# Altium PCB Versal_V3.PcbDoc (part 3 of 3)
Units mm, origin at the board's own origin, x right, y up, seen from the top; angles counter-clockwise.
Board outline 164.5 x 88.9 mm, 8 copper layers (Top Layer, Layer 2 [GND], Layer 3 [GND/OUT], Layer 4 [12V/GND], Layer 5 [GND/VOUT], Layer 6 [GND], Layer 7 [GND], Bottom Layer), stack 1.562 mm thick; 243 components, 69 nets, 695 pads, 1061 vias.
Unrouted connection lines stored in the file: 8.
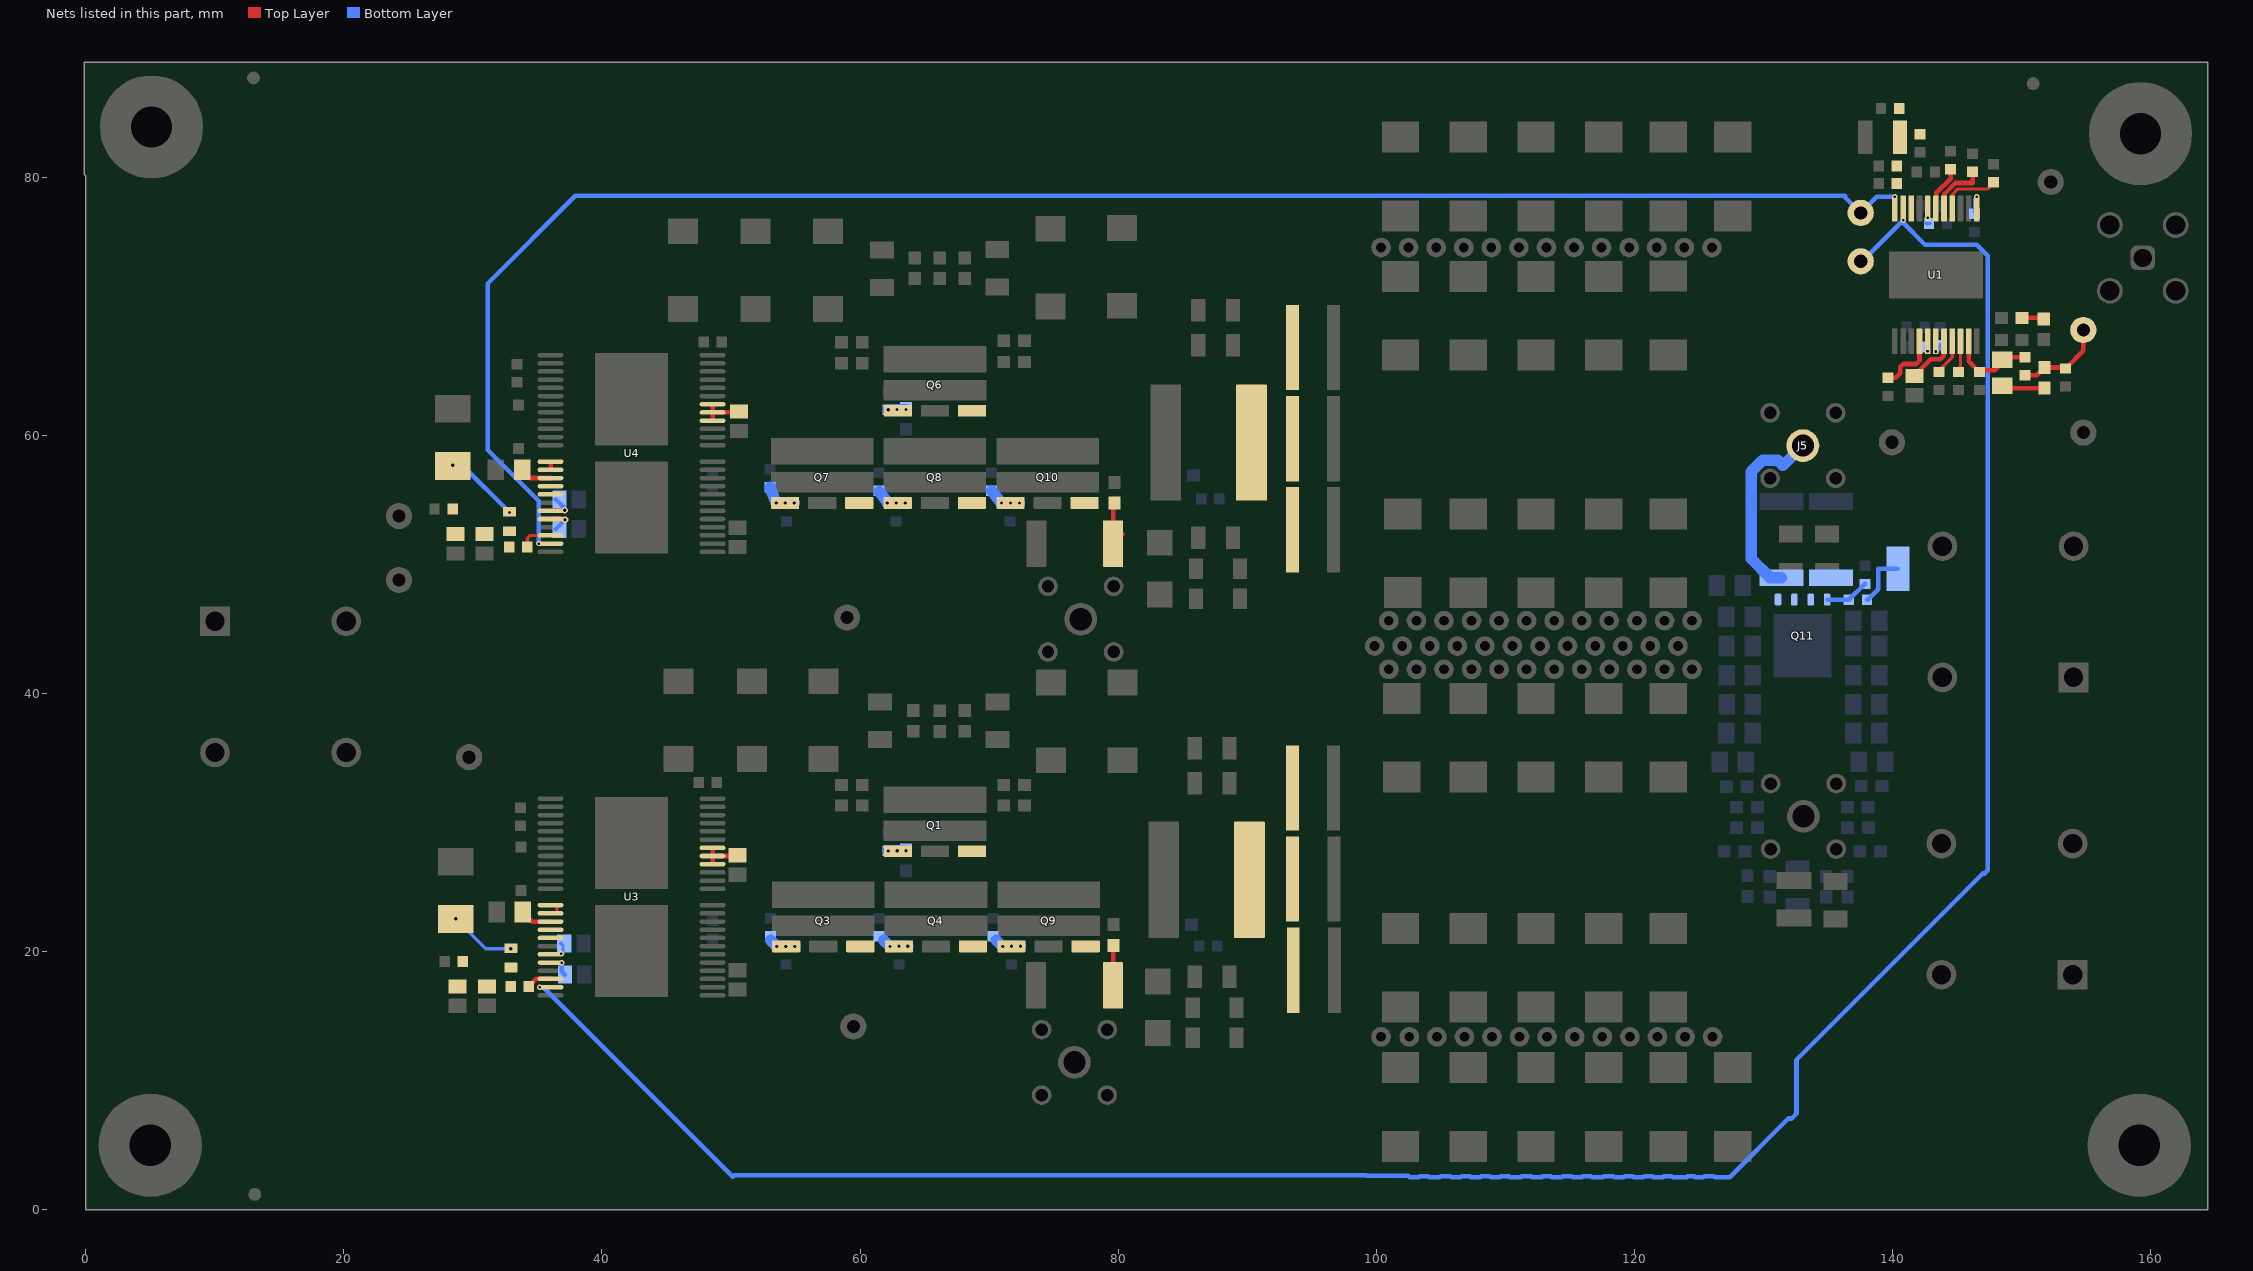
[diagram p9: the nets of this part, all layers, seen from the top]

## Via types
v1: diameter 0.508, hole 0.254, Top Layer to Bottom Layer, 951 vias
v2: diameter 0.5, hole 0.2, Top Layer to Bottom Layer, tented both sides, 60 vias
v3: diameter 0.5, hole 0.2, Top Layer to Bottom Layer, 34 vias
v4: diameter 0.406, hole 0.203, Top Layer to Bottom Layer, 16 vias

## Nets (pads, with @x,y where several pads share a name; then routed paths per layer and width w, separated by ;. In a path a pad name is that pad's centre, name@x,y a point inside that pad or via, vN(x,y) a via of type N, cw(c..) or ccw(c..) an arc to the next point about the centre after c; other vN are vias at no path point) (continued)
NetC1_1: C1.1 U1.18 | length 4
  Top Layer w0.356: C1.1@141.677,64.87 141.919,64.87 142.957,65.908 143.692,65.908 143.945,66.161 143.945,67.289 U1.18@143.981,67.289
NetC2_1: C2.1 C3.1 C4.1 R1.2 R2.2 U1.9
NetC6_1: C6.1 U1.5 | length 4.4
  Top Layer w0.356: U1.5@143.981,77.579 144.018,77.616 144.018,78.708 144.864,79.554 146.196,79.554 C6.1@146.196,80.318
NetC8_2: C8.2 U1.20 | length 2.3
  Top Layer w0.254: C8.2@145.097,65.017 145.251,65.172 U1.20@145.251,67.289
NetC9_2: C9.2 U1.15 | length 4.8
  Top Layer w0.356: C9.2@139.656,64.459 140.246,64.459 140.596,64.809 140.596,65.312 140.819,65.535 141.825,65.535 142.076,65.786 U1.15@142.076,67.289
NetC11_1: C11.1 R9.1 | length 1.5
  Top Layer w0.356: R9.1@149.936,69.103 151.207,69.103 C11.1@151.363,68.947
NetC18_1: C18.1 C19.1 R14.1 R23.1 R24.1 U3.16 U3.17
NetC20_1: C20.1 U3.15 | length 2.5
  Top Layer w0.356: C20.1@33.866,23.072 34.603,22.334 U3.15@36.017,22.334
NetC21_1: C21.1 U3.40 U3.41 U3.42 | length 3.2
  Top Layer w0.356: U3.40@48.567,26.779 U3.41@48.567,27.414 ; U3.42@48.567,28.049 U3.41@48.567,27.414 ; C21.1@50.497,27.468 50.443,27.414 U3.41@48.567,27.414
NetC25_1: C25.1 C26.1 R18.1 R45.1 R46.1 U4.16 U4.17
NetC27_1: C27.1 U4.15 | length 2.5
  Top Layer w0.356: C27.1@33.817,57.334 34.452,56.699 U4.15@36.017,56.699
NetC28_1: C28.1 U4.40 U4.41 U4.42 | length 3.3
  Top Layer w0.356: U4.40@48.567,61.144 U4.41@48.567,61.779 ; U4.42@48.567,62.414 U4.41@48.567,61.779 ; C28.1@50.605,61.85 50.534,61.779 U4.41@48.567,61.779
NetC89_1: C89.1 R67.1 | length 3.4
  Top Layer w0.356: C89.1@148.496,63.837 148.673,63.659 R67.1@151.773,63.659
NetC110_2: C110.2 R100.2 | length 4.2
  Top Layer w0.356: C110.2@79.714,54.761 79.611,54.658 R100.2@79.611,51.623 R100.2@80.329,52.341
NetC111_2: C111.2 R101.2 | length 2.9
  Top Layer w0.356: R101.2@79.608,17.6 79.608,20.468 C111.2@79.631,20.491
NetD1_2: D1.2 R23.2 | length 5.2
  Bottom Layer w0.254: v1(28.669,22.547) 30.99,20.225 v1(32.941,20.225)
NetD5_2: D5.2 R45.2 | length 6
  Top Layer w0.254: D5.2@28.429,57.644 v1(28.429,57.694)
  Bottom Layer w0.356: v1(28.429,57.694) 29.173,57.694 v1(32.842,54.025)
NetJ5_1: J5.1 Q11.1 Q11.2 Q11.3 R96.2 R97.2 | length 14.9
  Bottom Layer w0.889: R97.2@131.381,48.973 130.52,48.973 129.033,50.46 129.033,57.195 129.921,58.083 131.089,58.083 131.502,57.67 J5.1@133.045,59.213
NetL1_2: L1.2 R28.1 R29.1 R30.1
NetL2_2: L2.2 R31.1 R32.1 R33.1
NetQ1_1: Q1.1 Q1.2 R70.2 R71.2 | length 1.4
  Bottom Layer w0.889: R71.2@62.171,27.813 v1(62.867,27.813) v1(63.563,27.813)
  other v1: 62.178,27.8
NetQ3_1: Q3.1 Q3.2 R74.2 R75.2 | length 2.4
  Bottom Layer w0.356: R75.2@53.068,20.871 R75.2@53.068,21.188
  Bottom Layer w0.889: R75.2@53.068,20.871 v1(53.543,20.396) ; v1@53.543,20.409 v1(54.232,20.409) v1(54.928,20.409)
NetQ4_1: Q4.1 Q4.2 R76.2 R77.2 | length 2.1
  Bottom Layer w0.889: R77.2@61.841,20.875 v1(62.316,20.4) ; v1@62.316,20.413 v1(63.005,20.413) v1(63.701,20.413)
NetQ6_1: Q6.1 Q6.2 R83.2 R84.2 | length 1.4
  Bottom Layer w0.889: R84.2@62.164,62.003 v1(62.86,62.003) v1(63.556,62.003)
  other v1: 62.171,61.99
NetQ7_1: Q7.1 Q7.2 R87.2 R88.2 | length 2.4
  Bottom Layer w0.889: R88.2@53.024,55.986 v1(53.502,54.757) ; 53.84,54.77 v1(54.191,54.77) v1(54.887,54.77)
NetQ8_1: Q8.1 Q8.2 R89.2 R90.2 | length 2.2
  Bottom Layer w0.889: R90.2@61.498,55.63 61.973,54.98 ; v1@62.104,54.77 v1(62.793,54.77) v1(63.489,54.77)
  other v1: 62.104,54.757
NetQ9_1: Q9.1 Q9.2 R78.2 R79.2 | length 2.1
  Bottom Layer w0.889: R79.2@70.566,20.875 v1(71.041,20.4) ; v1@71.041,20.413 v1(71.73,20.413) v1(72.426,20.413)
NetQ10_1: Q10.1 Q10.2 R91.2 R92.2 | length 2.6
  Bottom Layer w0.889: R92.2@70.196,55.705 v1(70.958,54.757) ; v1@70.958,54.77 v1(71.647,54.77) v1(72.343,54.77)
NetQ11_4: Q11.4 R94.2 R95.2 | length 3.4
  Bottom Layer w0.356: Q11.4@134.924,47.281 136.597,47.281 R94.2@136.61,47.268 137.833,48.491 R95.2@137.86,48.491
NetR3_1: R3.1 U1.16
  other v4: 142.704,66.527
NetR4_1: R4.1 R7.2 R67.2 TP5.1 | length 6.9
  Top Layer w0.356: R7.2@150.24,64.657 151.171,64.657 R67.2@151.773,65.259 R4.1@153.373,65.259 ; R4.1@153.4,65.186 154.771,66.557 TP5.1@154.771,68.172
NetR5_1: R5.1 U1.17 | length 0.6
  Bottom Layer w0.356: v4(143.346,66.497) 143.67,66.821 R5.1@143.67,66.997
NetR8_1: R8.1 U1.1 | length 1.3
  Bottom Layer w0.254: R8.1@146.347,77.265 146.347,78.309 v4(146.524,78.486)
NetR11_2: R11.2 U1.4 | length 4.6
  Top Layer w0.254: U1.4@144.616,77.579 144.616,78.657 145.056,79.097 147.404,79.097 R11.2@147.825,79.518
NetR12_2: R12.2 U1.7 | length 1.4
  Top Layer w0.356: U1.7@142.711,77.579 142.711,76.88 v4(142.715,76.877)
  Bottom Layer w0.356: v4(142.715,76.877) 142.641,76.803 142.641,76.433 R12.2@142.816,76.433
NetR13_2: R13.2 U1.19 | length 2.7
  Top Layer w0.254: R13.2@143.58,65.017 144.616,66.053 U1.19@144.616,67.289
NetR14_2: R14.2 U3.22 | length 1.9
  Top Layer w0.356: R14.2@34.33,17.298 34.922,17.889 U3.22@36.017,17.889
NetR15_2: R15.2 U3.19 | length 0.9
  Bottom Layer w0.254: R15.2@36.81,20.644 36.986,20.469 v4@36.986,19.778
  other v4: 36.84,19.836
NetR16_2: R16.2 U3.20 | length 1
  Bottom Layer w0.356: v4(36.876,19.15) 36.876,18.478 R16.2@37.126,18.229
NetR18_2: R18.2 U4.22 | length 2.6
  Top Layer w0.254: R18.2@34.221,51.352 34.221,52.015 34.461,52.254 U4.22@36.017,52.254
NetR19_2: R19.2 U4.19 | length 2.2
  Top Layer w0.356: U4.19@36.017,54.159 37.07,54.159 v1(37.119,54.208)
  Bottom Layer w0.356: R19.2@36.434,55.034 37.119,54.35 v1(37.119,54.208)
NetR20_2: R20.2 U4.20 | length 2.1
  Top Layer w0.356: U4.20@36.017,53.524 37.066,53.524 v1(37.134,53.455)
  Bottom Layer w0.356: R20.2@36.434,52.752 37.134,53.452 v1(37.134,53.455)
NetR94_1: R94.1 TP13.1 | length 4.3
  Bottom Layer w0.356: R94.1@138.01,47.268 138.071,47.268 138.891,48.089 138.891,49.659 140.4,49.659 TP13.1@140.4,49.663
NetR99_1: R99.1 U1.6 | length 3.5
  Top Layer w0.356: U1.6@143.346,77.579 143.346,78.292 143.383,78.329 143.383,78.791 144.486,79.894 R99.1@144.486,80.621
NetU3_13: U3.13 U3.14 | length 0.6
  Top Layer w0.254: U3.14@36.518,22.969 U3.13@36.518,23.604
NetU4_13: U4.13 U4.14 | length 0.6
  Top Layer w0.356: U4.14@36.017,57.334 U4.13@36.017,57.969
OUTA: TP3.1 U1.10 U3.23 | length 191.7
  Bottom Layer w0.356: v4(35.172,17.254) 35.436,17.254 50.13,2.56 50.237,2.667 99.193,2.667 99.221,2.638 102.478,2.638 102.58,2.536 103.297,2.536 103.373,2.612 104.004,2.612 104.08,2.536 104.913,2.536 104.989,2.612 105.735,2.612 105.811,2.536 106.528,2.536 106.604,2.612 107.235,2.612 107.311,2.536 108.047,2.536 108.123,2.612 108.773,2.612 108.849,2.536 109.566,2.536 109.642,2.612 110.273,2.612 110.349,2.536 111.182,2.536 111.258,2.612 112.003,2.612 112.08,2.536 112.797,2.536 112.873,2.612 113.503,2.612 113.58,2.536 114.359,2.536 114.435,2.612 115.127,2.612 115.203,2.536 115.921,2.536 115.997,2.612 116.627,2.612 116.703,2.536 117.536,2.536 117.612,2.612 118.358,2.612 118.434,2.536 119.152,2.536 119.228,2.612 119.858,2.612 119.934,2.536 120.671,2.536 120.747,2.612 121.396,2.612 121.472,2.536 122.19,2.536 122.266,2.612 122.896,2.612 122.972,2.536 124.025,2.536 124.101,2.612 124.627,2.612 124.703,2.536 125.316,2.536 125.392,2.612 126.127,2.612 126.203,2.536 127.375,2.536 131.917,7.079 132.18,7.079 132.552,7.451 132.552,11.629 146.984,26.061 147.133,26.061 147.372,26.3 147.372,73.935 146.524,74.784 142.503,74.784 140.82,76.466 v4(140.82,76.679) 137.634,73.492 TP3.1@137.524,73.492
OUTB: TP4.1 U1.11 U4.23 | length 134.6
  Bottom Layer w0.356: v4(35.095,51.619) 35.095,54.922 31.15,58.867 31.15,71.768 37.943,78.562 136.305,78.562 ; 136.305,78.461 TP4.1@137.524,77.242 138.768,78.486 v4(140.171,78.486)
VSENSE: C89.2 R7.1 R10.2 U1.21 | length 6.8
  Top Layer w0.356: U1.21@145.886,67.289 145.886,65.759 R10.2@146.728,64.917 146.728,65.034 147.927,65.034 148.496,65.603 148.95,66.057 R7.1@150.24,66.057
pads on no net: FID1.1 FID2.1 FID3.1 H1.1 H2.1 H3.1 H4.1 H5.0 H6.0 H7.0 H8.0 LBL1.0 Q11.9@131.589,42.866 Q11.9@131.589,44.206 Q11.9@131.589,45.546 Q11.9@133.019,42.866 Q11.9@133.019,44.106 Q11.9@133.019,44.206 Q11.9@133.019,45.546 Q11.9@134.449,42.866 Q11.9@134.449,44.206 Q11.9@134.449,45.546 U1.2 U1.3 U1.12 U1.13

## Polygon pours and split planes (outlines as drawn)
GND on Top Layer "TOP_LAYER_GND_P012" (solid, pour order 12): 73.637,33.483 73.296,33.824 73.296,33.858 72.43,33.858 71.832,33.26 71.832,30.396 72.276,29.985 73.381,29.985 73.637,30.24
GND on Top Layer "TOP_LAYER_GND_P015" (solid, pour order 15): 57.629,30.369 57.97,30.028 57.97,29.994 58.836,29.994 59.433,30.591 59.433,33.456 58.99,33.867 57.885,33.867 57.629,33.611
GND on Top Layer "TOP_LAYER_GND_P019" (solid, pour order 19): 73.803,68.047 73.462,68.388 73.462,68.422 72.596,68.422 71.999,67.825 71.999,64.96 72.442,64.549 73.547,64.549 73.803,64.805
GND on Top Layer "TOP_LAYER_GND_P018" (solid, pour order 18): 57.413,64.864 57.754,64.523 57.754,64.49 58.62,64.49 59.217,65.087 59.217,67.952 58.774,68.362 57.668,68.362 57.413,68.107
GND on Top Layer "TOP_LAYER_GND_P102" (solid, remove dead copper, pour order 102): 136.61,58.224 136.538,58.296 130.469,58.296 129.431,57.258 129.431,53.88 132.123,51.187 136.61,51.187 136.61,40.269 138.195,38.684 161.381,38.684 163.4,40.683 163.4,87.219 136.61,87.219
GND on Top Layer "TOP_LAYER_GND_P098" (solid, remove dead copper, pour order 98): 98.074,46.488 101.387,49.801 126.308,49.801 127.492,48.617 127.492,37.958 126.483,36.95 101.572,36.95 98.074,40.447
NetL1_2 on Top Layer "TOP_LAYER_NETL1_2_P093" (solid, remove dead copper, pour order 93): 88.842,20.934 92.291,17.486 92.291,13.832 94.29,13.832 94.29,38.497 92.569,38.497 92.569,34.349 88.842,30.623
ASW1 on Top Layer "TOP_LAYER_ASW1_P086" (solid, remove dead copper, pour order 86): 32.905,24.675 33.716,23.863 49.932,23.863 49.932,23.613 52.095,21.45 80.542,21.45 80.542,17.977 82.989,15.531 85.514,15.531 85.514,30.128 50.304,30.128 49.752,29.575 49.752,26.297 47.709,26.297 47.313,26.694 47.313,32.491 33.793,32.491 32.905,31.603
BP5L1 on Top Layer "TOP_LAYER_BP5L1_P022" (solid, pour order 22): 47.322,19.775 47.556,20.008 52.18,20.008 52.397,19.791 52.397,18.35 52.119,18.072 47.567,18.072 47.322,18.316 47.322,19.775
BP5L2 on Top Layer "TOP_LAYER_BP5L2_P037" (solid, pour order 37): 47.347,54.173 47.581,54.406 52.205,54.406 52.422,54.189 52.422,52.748 52.144,52.47 47.592,52.47 47.347,52.714 47.347,54.173
GND on Top Layer "TOP_LAYER_GND_P099" (solid, remove dead copper, pour order 99): 126.386,70.939 126.828,70.497 126.828,66.174 128.154,64.848 131.091,64.848 133.111,66.869 133.111,78.071 131.344,79.839 101.2,79.839 99.772,78.41 99.772,72.369 101.202,70.939
GND on Top Layer "TOP_LAYER_GND_P101" (solid, remove dead copper, pour order 101): 125.38,17.872 126.205,18.697 126.205,22.42 126.932,23.147 136.638,23.147 136.638,15.35 128.321,8.887 101.64,8.887 99.849,10.677 99.849,16.719 101.003,17.872
ASW2 on Top Layer "TOP_LAYER_ASW2_P083" (solid, remove dead copper, pour order 83): 79.451,55.912 79.451,51.672 80.227,50.897 84.94,50.897 84.94,64.113 49.76,64.113 49.76,61.851 49.76,61.013 47.585,61.013 47.585,66.734 33.193,66.734 33.003,66.541 33.003,58.798 33.741,58.059 49.426,58.059 51.555,56.002
GND on Top Layer "TOP_LAYER_GND_P103" (solid, remove dead copper, pour order 103): 87.275,-0.088 0,-0.088 0,88.312 87.275,88.312
LOL_GATE4 on Top Layer "TOP_LAYER_LOL_GATE4_P051" (solid, pour order 51): 47.377,58.008 47.61,58.241 52.235,58.241 52.452,58.024 52.452,56.583 52.174,56.305 47.621,56.305 47.377,56.549 47.377,58.008
LOH_GATE2 on Top Layer "TOP_LAYER_LOH_GATE2_P053" (solid, pour order 53): 47.347,21.711 47.581,21.945 52.205,21.945 52.422,21.728 52.422,20.286 52.144,20.008 47.592,20.008 47.347,20.253 47.347,21.711
HOH_GATE3 on Top Layer "TOP_LAYER_HOH_GATE3_P054" (solid, pour order 54): 47.377,64.356 47.61,64.59 52.235,64.59 52.452,64.373 52.452,62.932 52.174,62.654 47.621,62.654 47.377,62.898 47.377,64.357
HOL_GATE3 on Top Layer "TOP_LAYER_HOL_GATE3_P063" (solid, pour order 63): 48.2,66.622 48.297,66.719 48.297,67.734 48.553,67.99 49.435,67.99 49.627,67.798 49.627,66.829 49.852,66.605 52.259,66.622 52.476,66.405 52.476,64.963 52.197,64.684 47.647,64.684 47.401,64.93 47.401,66.405 47.639,66.622
HOH_GATE1 on Top Layer "TOP_LAYER_HOH_GATE1_P064" (solid, pour order 64): 47.377,29.991 47.61,30.225 52.235,30.225 52.452,30.008 52.452,28.566 52.174,28.288 47.621,28.288 47.377,28.533 47.377,29.991
HOL_GATE1 on Top Layer "TOP_LAYER_HOL_GATE1_P066" (solid, pour order 66): 48.2,32.257 48.297,32.354 48.297,33.369 48.553,33.625 49.435,33.625 49.627,33.433 49.627,32.464 49.852,32.239 52.259,32.257 52.476,32.04 52.476,30.598 52.197,30.319 47.647,30.319 47.401,30.565 47.401,32.04 47.639,32.257
BOOT1 on Top Layer "TOP_LAYER_BOOT1_P020" (solid, remove dead copper, pour order 20): 34.404,28.786 34.581,28.963 36.99,28.963 36.99,30.192 36.812,30.37 27.386,30.37 27.051,30.034 27.037,25.607 34.404,25.607
NetL2_2 on Top Layer "TOP_LAYER_NETL2_2_P071" (solid, remove dead copper, pour order 71): 88.82,54.3 88.893,54.3 91.573,51.62 91.573,47.182 93.096,47.182 94.306,48.392 94.306,71.848 92.445,71.848 92.445,67.988 88.82,64.363
NetC25_1 on Top Layer "TOP_LAYER_NETC25_1_P072" (solid, remove dead copper, pour order 72): 27.729,55.992 28.054,56.318 37.083,56.318 37.376,56.025 37.376,55.384 36.98,54.988 32.117,54.988 32.117,53.325 32.446,53.325 32.517,53.254 32.588,53.325 33.167,53.325 33.317,53.175 33.317,50.963 33.182,50.827 32.321,50.827 32.321,51.778 28.17,51.778 27.729,52.22
BOOT2 on Top Layer "TOP_LAYER_BOOT2_P073" (solid, remove dead copper, pour order 73): 37.327,64.807 37.478,64.655 37.478,63.425 37.384,63.331 34.631,63.331 34.622,63.321 34.622,59.139 27.132,59.139 26.794,59.477 26.81,64.807
NetC18_1 on Top Layer "TOP_LAYER_NETC18_1_P082" (solid, remove dead copper, pour order 82): 28.187,21.746 28.422,21.981 37.633,21.981 37.834,21.779 37.834,21.138 37.438,20.742 32.576,20.742 32.576,19.079 32.905,19.079 32.972,19.079 33.047,19.079 33.626,19.079 34.09,18.615 34.09,17.031 33.64,16.581 32.78,16.581 28.666,16.581 28.187,17.06
12V on Top Layer "TOP_LAYER_12V_P088" (solid, remove dead copper, pour order 88): 71.728,62.69 71.728,67.787 72.479,68.539 82.277,68.539 82.786,69.013 82.786,72.913 2.688,72.913 2.857,60.904 2.857,29.363 16.7,29.363 16.7,51.077 25.568,51.077 27.151,52.66 27.386,52.66 27.386,62.667 27.254,62.69
12V on Top Layer "TOP_LAYER_12V_P089" (solid, remove dead copper, pour order 89): 72.09,29.467 72.09,32.92 72.43,33.26 82.484,33.26 83.129,33.906 83.129,38.344 31.468,38.344 31.468,41.665 29.52,43.613 2.897,43.613 2.738,40.832 2.897,29.467 2.738,29.307 2.738,19.316 3.866,18.187 28.369,18.187 28.369,29.425 28.52,29.467
NetC2_1 on Top Layer "TOP_LAYER_NETC2_1_P092" (solid, remove dead copper, pour order 92): 140.04,85.889 139.802,85.651 139.802,79.061 139.802,76.546 142.776,76.546 142.776,85.729 142.616,85.889
0V8 on Top Layer "TOP_LAYER_0V8_P104" (solid, remove dead copper, pour order 104): 87.612,88.666 164.468,88.666 164.468,1.061 87.612,1.061
LOL_GATE2 on Top Layer "TOP_LAYER_LOL_GATE2_P041" (solid, pour order 41): 47.377,23.641 47.61,23.875 52.235,23.875 52.452,23.658 52.452,22.216 52.174,21.938 47.621,21.938 47.377,22.183 47.377,23.641
LOH_GATE4 on Top Layer "TOP_LAYER_LOH_GATE4_P048" (solid, pour order 48): 47.347,56.078 47.581,56.311 52.205,56.311 52.422,56.094 52.422,54.653 52.144,54.375 47.592,54.375 47.347,54.619 47.347,56.078
GND on Layer 2 [GND] "LAYER_2_[GND]_GND_P052" (solid, remove dead copper, pour order 52): 0,88.9 0,-0.128 164.272,-0.128 164.506,0.106 164.506,88.969 0.069,88.969
GND on Layer 7 [GND] "LAYER_7_[GND]_GND_P056" (solid, remove dead copper, pour order 56): 0.547,88.253 163.753,88.253 163.753,0.647 0.647,0.647 0.647,88.153
GND on Layer 3 [GND/OUT] "LAYER_3_[GND/OUT]_GND_P067" (solid, remove dead copper, pour order 67): 0.697,88.203 0.807,88.312 89.911,88.312 89.911,0.754 89.804,0.647 0.647,0.647 0.647,88.153
0V8 on Layer 3 [GND/OUT] "LAYER_3_[GND/OUT]_0V8_P057" (solid, remove dead copper, pour order 57): 87.549,88.253 163.753,88.253 163.753,0.647 87.549,0.647
GND on Layer 5 [GND/VOUT] "LAYER_5_[GND/VOUT]_GND_P069" (solid, remove dead copper, pour order 69): 0.804,88.253 90.1,88.253 90.1,0.739 90.192,0.647 0.647,0.647 0.647,88.153 0.697,88.203
0V8 on Layer 5 [GND/VOUT] "LAYER_5_[GND/VOUT]_0V8_P058" (solid, remove dead copper, pour order 58): 87.549,88.253 163.753,88.253 163.753,0.647 87.549,0.647
12V on Layer 4 [12V/GND] "LAYER_4_[12V/GND]_12V_P060" (solid, remove dead copper, pour order 60): 83.883,39.024 83.203,38.344 21.9,38.344 21.9,60.075 25.412,63.586 83.883,63.586 83.883,70.47 0.694,70.47 0.694,29.807 83.883,29.807
GND on Layer 4 [12V/GND] "LAYER_4_[12V/GND]_GND_P068" (solid, remove dead copper, pour order 68): 0.647,88.153 0.747,88.253 163.753,88.253 163.753,0.647 0.647,0.647 0.647,88.153 0.697,88.203
0V8 on Bottom Layer "BOTTOM_LAYER_0V8_P077" (solid, pour order 77): 130.408,46.558 129.706,47.26 129.706,49.435 129.431,49.71 127.653,49.71 127.653,49.666 127.38,49.393 127.38,25.735 127.275,25.63 128.021,24.885 128.021,24.693 137.406,24.693 138.335,25.621 138.335,46.558
NetJ5_1 on Bottom Layer "BOTTOM_LAYER_NETJ5_1_P097" (solid, remove dead copper, pour order 97): 130.814,46.845 136.933,46.845 136.933,50.179 130.239,50.179 129.706,49.646 129.706,46.845
LOL_GATE4 on Bottom Layer "BOTTOM_LAYER_LOL_GATE4_P081" (solid, pour order 81): 47.356,58.008 47.59,58.241 52.214,58.241 52.431,58.024 52.431,56.583 52.153,56.305 47.601,56.305 47.356,56.549 47.356,58.008
LOH_GATE4 on Bottom Layer "BOTTOM_LAYER_LOH_GATE4_P080" (solid, pour order 80): 49.372,56.336 52.214,56.336 52.431,56.119 52.431,54.678 52.153,54.4 49.372,54.4
HOL_GATE3 on Bottom Layer "BOTTOM_LAYER_HOL_GATE3_P087" (solid, pour order 87): 47.401,66.388 47.635,66.622 52.259,66.622 52.476,66.405 52.476,64.964 52.198,64.686 47.645,64.686 47.401,64.93 47.401,66.389
HOH_GATE3 on Bottom Layer "BOTTOM_LAYER_HOH_GATE3_P085" (solid, pour order 85): 47.377,64.356 47.61,64.59 52.235,64.59 52.452,64.373 52.452,62.932 52.174,62.654 47.621,62.654 47.377,62.898 47.377,64.357
LOH_GATE2 on Bottom Layer "BOTTOM_LAYER_LOH_GATE2_P062" (solid, pour order 62): 49.372,21.97 52.214,21.97 52.431,21.753 52.431,20.311 52.153,20.033 49.372,20.033
LOL_GATE2 on Bottom Layer "BOTTOM_LAYER_LOL_GATE2_P090" (solid, pour order 90): 47.356,23.641 47.59,23.875 52.214,23.875 52.431,23.658 52.431,22.216 52.153,21.938 47.601,21.938 47.356,22.183 47.356,23.641
HOH_GATE1 on Bottom Layer "BOTTOM_LAYER_HOH_GATE1_P091" (solid, pour order 91): 47.377,29.991 47.61,30.225 52.235,30.225 52.452,30.008 52.452,28.566 52.174,28.288 47.621,28.288 47.377,28.533 47.377,29.991
HOL_GATE1 on Bottom Layer "BOTTOM_LAYER_HOL_GATE1_P096" (solid, pour order 96): 47.401,32.023 47.635,32.257 52.259,32.257 52.476,32.04 52.476,30.599 52.198,30.32 47.645,30.32 47.401,30.565 47.401,32.023
GND on Bottom Layer "BOTTOM_LAYER_GND_P100" (solid, remove dead copper, pour order 100): 0.683,88.331 0.783,88.431 163.788,88.431 163.788,0.825 0.683,0.825 0.683,88.331 0.583,88.431
GND on Layer 6 [GND] "LAYER_6_[GND]_GND_P070" (solid, remove dead copper, pour order 70): 0.752,88.257 0.757,88.253 163.753,88.253 163.753,0.647 0.647,0.647 0.647,88.153

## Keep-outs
Keep-Out Layer:
  text ".Layer_Name" at 14.656,-21.806 h1.52

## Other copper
Top Layer:
  pour cut-out: 139.373,75.665 147.319,75.665 147.319,69.204 139.373,69.204
  text ".Layer_Name" at 14.656,-21.806 h1.52
Bottom Layer:
  text ".Layer_Name" at 14.656,-21.806 h1.52

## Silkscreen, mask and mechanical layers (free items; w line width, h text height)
Top Overlay:
  text "TIDA-010958" at 21.667,7.594 h1.5
  text ".Layer_Name" at 14.656,-21.806 h1.52
Bottom Overlay:
  text ".Layer_Name" at 14.656,-21.806 h1.52
Top Paste:
  text ".Layer_Name" at 14.656,-21.806 h1.52
Bottom Paste:
  text ".Layer_Name" at 14.656,-21.806 h1.52
Top Solder:
  text ".Layer_Name" at 14.656,-21.806 h1.52
  text ".Layer_Name" at 14.656,-21.806 h1.52
Bottom Solder:
  text ".Layer_Name" at 14.656,-21.806 h1.52
Drill Guide:
  text ".Layer_Name" at 14.656,-21.806 h1.52
M1 Board Outline:
  lines w0.254: 0,-0.088 164.4,0 164.506,88.969 118.5,88.875 ; 0,0 0,88.697 ; 0,88.9 98.477,88.875 ; 99.073,88.955 110.195,88.98 119.095,88.955
  text ".Layer_Name" at 14.656,-21.806 h1.52
M2 Board Dimensions:
  rectangle: 0,-6.985 3.175,-3.81
  rectangle: 3.175,-10.16 12.7,-6.985
  lines w0.178: 0,-6.985 25.4,-6.985 ; 3.175,-10.16 3.175,-3.81 ; 6.35,-10.16 6.35,-3.81 ; 12.7,-10.16 12.7,-3.81 ; 19.05,-10.16 19.05,-3.81 ; 0,-10.16 0,-3.81 25.4,-3.81 25.4,-10.16 0,-10.16
  text ".Layer_Name" at 14.656,-21.806 h1.52
M3 3D STEP Top:
  text ".Layer_Name" at 14.656,-21.806 h1.52
M4 3D STEP Bottom:
  text ".Layer_Name" at 14.656,-21.806 h1.52
M5 Assembly Top:
  lines w0.254: -7.417,-23.626 160.223,-23.626 ; -7.417,-18.462 160.274,-18.462 ; -7.417,-13.297 -7.417,-28.791 94.31,-28.791 160.274,-28.791 160.274,-13.297 -7.404,-13.297 -7.404,-28.791 32.614,-28.791 ; 55.194,-28.791 55.194,-13.297 ; 87.376,-18.462 87.376,-13.297 ; 108.712,-18.462 108.712,-13.297 ; 124.511,-28.956 124.511,-23.804
  text "COMPONENTS MARKED 'DNP' SHOULD NOT BE POPULATED." at 29.299,-8.09 h0.64
  text "ASSEMBLY VARIANT:" at 29.286,-11.024 h0.64
  text ".VariantName" at 55.601,-11.024 h0.64
  text "PCB VIEWED FROM TOP SIDE" at -5.804,-16.654 h1.52
  text "BOARD #:" at 57.099,-16.654 h1.52
  text ".PRJ_Number" at 70.955,-16.654 h1.52
  text "REV:" at 92.405,-16.654 h1.52
  text ".PCB_Rev" at 99.809,-16.654 h1.52
  text "SVN REV:" at 113.69,-16.654 h1.52
  text ".VersionControl_RevNumber" at 126.543,-16.654 h1.52
  text "TID #:" at 57.099,-21.819 h1.52
  text ".TID" at 70.955,-21.819 h1.52
  text "PLOT NAME =" at -5.804,-27.034 h1.52
  text ".plot_File_Name" at 14.656,-27.034 h1.52
  text "GENERATED    :" at 57.15,-27.034 h1.52
  text ".Print_Date" at 79.235,-27.034 h1.52
  text ".Print_Time" at 97.752,-27.034 h1.52
  text "TEXAS INSTRUMENTS" at 129.87,-27.034 h1.52
M6 Assembly Bottom:
  lines w0.254: -7.429,-18.474 160.261,-18.474 ; -7.379,-23.639 160.261,-23.639 ; 28.334,-28.969 28.334,-23.817 ; 44.133,-18.474 44.133,-13.31 ; 65.468,-18.474 65.468,-13.31 ; 97.65,-28.804 97.65,-13.31 ; 120.231,-28.804 160.249,-28.804 160.249,-13.31 -7.429,-13.31 -7.429,-28.804 58.534,-28.804 160.261,-28.804 160.261,-13.31
  text "COMPONENTS MARKED 'DNP' SHOULD NOT BE POPULATED." at 154.991,-8.077 h0.64
  text ".VariantName" at 128.473,-11.024 h0.64
  text "ASSEMBLY VARIANT:" at 154.864,-11.024 h0.64
  text ".VersionControl_RevNumber" at 26.302,-16.667 h1.52
  text "SVN REV:" at 39.154,-16.667 h1.52
  text ".PCB_Rev" at 53.035,-16.667 h1.52
  text "REV:" at 60.439,-16.667 h1.52
  text ".PRJ_Number" at 81.89,-16.667 h1.52
  text "BOARD #:" at 95.745,-16.667 h1.52
  text "PCB VIEWED FROM BOTTOM SIDE" at 158.648,-16.667 h1.52
  text ".TID" at 81.89,-21.831 h1.52
  text "TID #:" at 95.745,-21.831 h1.52
  text "TEXAS INSTRUMENTS" at 22.974,-27.047 h1.52
  text ".Print_Time" at 55.093,-27.047 h1.52
  text ".Print_Date" at 73.609,-27.047 h1.52
  text "GENERATED    :" at 95.694,-27.047 h1.52
  text ".plot_File_Name" at 138.189,-27.047 h1.52
  text "PLOT NAME =" at 158.648,-27.047 h1.52
M9 Title Sheet:
  drawing of 57 lines, arcs and shapes, not listed
  text "1" at 18.792,204.127 h1.78
  text "2" at 82.182,204.127 h1.78
  text "3" at 145.411,204.127 h1.78
  text "4" at 209.08,204.127 h1.78
  text "5" at 272.555,204.127 h1.78
  text "6" at 336.182,204.127 h1.78
  text "A" at -10.579,175.095 h1.78
  text "A" at 365.341,175.095 h1.78
  text "B" at -10.579,114.643 h1.78
  text "B" at 365.341,114.643 h1.78
  text "C" at -10.579,54.318 h1.78
  text "C" at 365.341,54.318 h1.78
  text "PROJECT TITLE:" at 288.125,7.048 h1.14
  text ".PRJ_Title" at 289.395,3.662 h1.78
  text "DESIGNED FOR:" at 288.125,-0.597 h1.14
  text ".PRJ_Customer" at 289.395,-4.153 h1.78
  text "D" at -10.579,-5.88 h1.78
  text "D" at 365.341,-5.88 h1.78
  text "FILE NAME:" at 288.125,-8.217 h1.14
  text ".PCB_File_Name_No_Path" at 289.395,-11.265 h1.78
  text "Texas Instruments (TI) and/or its licensors do not warrant the accuracy or completeness of this specification" at 161.9,-15.376 h1.14
  text "ENGINEER:" at 288.125,-15.583 h1.14
  text "LAYOUT BY:" at 326.352,-15.583 h1.14
  text "or any information contained therein. TI and/or its licensors do not warrant that this design will meet" at 160.757,-18.237 h1.14
  text ".PRJ_Engineer" at 289.395,-19.52 h1.78
  text ".PCB_Layout" at 327.635,-19.52 h1.78
  text "the specifications, will be suitable for your application or fit for any particular purpose, or will operate in" at 160.757,-21.099 h1.14
  text ".Layer_Name" at 14.656,-21.806 h1.52
  text "ALTIUM DESIGNER VERSION:" at 326.352,-23.457 h1.14
  text "an implementation. TI and/or its licensors do not warrant that the design is production worthy. You should" at 160.757,-23.961 h1.14
  text "completely validate and test your design implementation to confirm the system functionality for your application." at 161.9,-26.822 h1.14
  text ".print_Scale" at 289.395,-26.843 h1.78
  text ".Application_BuildNumber" at 327.635,-26.843 h1.78
  text "1" at 18.792,-32.093 h1.78
  text "2" at 82.182,-32.093 h1.78
  text "3" at 145.411,-32.093 h1.78
  text "4" at 209.08,-32.093 h1.78
  text "5" at 272.555,-32.093 h1.78
  text "6" at 336.182,-32.093 h1.78
M10 Fab Notes:
  drawing of 189 lines, arcs and shapes, not listed
  text "DESIGN INFORMATION" at 314.503,161.447 h1.52
  text "MIN. TRACK WIDTH:" at 298.131,158.091 h1.52
  text "8" at 325.976,158.091 h1.52
  text "MIL" at 329.907,158.091 h1.52
  text "7.874" at 321.75,155 h1.52
  text "MIN. CLEARANCE:" at 298.131,154.938 h1.52
  text "MIL" at 329.907,154.938 h1.52
  text "MIN. VIA PAD SIZE:" at 298.131,151.785 h1.52
  text "24" at 325.214,151.785 h1.52
  text "MIL" at 329.907,151.785 h1.52
  text "0.05mm (2MIL)" at 315.784,148.486 h1.52
  text "MINIMUM ANNULAR RING" at 289.769,148.277 h1.52
  text "EXTERNAL" at 333.768,148.277 h1.52
  text "PER" at 294.849,145.48 h1.52
  text "IPC-D-275 CLASS 2 LEVEL C" at 300.437,145.48 h1.52
  text "MIL, HOLES" at 338.238,142.928 h1.52
  text "+/-" at 328.27,142.709 h1.52
  text "+/-" at 349.961,142.709 h1.52
  text "REGISTRATION TOLERANCES:" at 289.769,142.682 h1.52
  text "METAL" at 320.243,142.682 h1.52
  text "5" at 334.879,142.683 h1.52
  text "3" at 356.037,142.683 h1.52
  text "MIL" at 358.99,142.682 h1.52
  text "HOLE SIZE TOLERANCE (UNLESS OTHERWISE SPECIFIED):" at 289.769,140.185 h1.52
  text "+/-" at 349.961,140.112 h1.52
  text "3" at 356.037,140.085 h1.52
  text "MIL" at 358.99,140.085 h1.52
  text "MATERIAL:" at 287.87,136.589 h1.52
  text "FR-4 High Tg" at 312.926,133.324 h1.52
  text "X" at 309.257,133.122 h1.52
  text "FR-4" at 298.563,133.007 h1.52
  text "OTHER" at 336.358,133.007 h1.52
  text "62 MIL (1.6mm) +/-10%" at 306.694,129.374 h1.52
  text "X" at 303.643,129.312 h1.52
  text "THICKNESS:" at 289.769,129.165 h1.52
  text "OTHER" at 339.33,129.165 h1.52
  text "TOLERANCE:" at 289.769,125.652 h1.52
  text "X" at 311.314,125.652 h1.52
  text "ANSI IPC-6012 TYPE 3 CLASS 2" at 315.836,125.652 h1.52
  text "OTHER +/-" at 315.835,121.989 h1.52
  text "BOW & TWIST:" at 289.769,118.302 h1.52
  text "X" at 311.314,118.302 h1.52
  text "ANSI IPC-6012 TYPE 3 CLASS 2" at 315.836,118.302 h1.52
  text "OTHER +/-" at 315.835,114.576 h1.52
  text "DRILLING:" at 287.87,111.258 h1.52
  text "NC_DRILL FILES" at 332.599,108.586 h1.52
  text "REFERENCE:" at 289.769,108.486 h1.52
  text "X" at 306.463,108.484 h1.52
  text "AS SHOWN" at 310.984,108.486 h1.52
  text "X" at 329.348,108.486 h1.52
  text "OTHER" at 340.168,104.873 h1.52
  text "PTH COPPER THICKNESS:" at 289.761,104.783 h1.52
  text "X" at 318.697,104.783 h1.52
  text "20-30 um" at 321.948,104.783 h1.52
  text "BOARD FINISH:" at 287.87,101.034 h1.52
  text "SILKSCREEN:" at 291.812,98.237 h1.52
  text "X" at 316.14,98.237 h1.52
  text "TOP" at 319.112,98.237 h1.52
  text "X" at 329.094,98.237 h1.52
  text "BOTTOM" at 332.091,98.237 h1.52
  text "SILKSCREEN COLOR:" at 291.812,94.295 h1.52
  text "X" at 316.115,94.295 h1.52
  text "WHITE" at 319.112,94.295 h1.52
  text "OTHER" at 332.091,94.295 h1.52
  text "GREEN" at 322.439,90.652 h1.52
  text "X" at 334.326,90.652 h1.52
  text "RED" at 338.136,90.652 h1.52
  text "SOLDER RESIST COLOR:" at 291.812,90.477 h1.52
  text "X" at 319.442,86.734 h1.52
  text "MATTE" at 322.439,86.734 h1.52
  text "SEMI-GLOSS" at 338.125,86.717 h1.52
  text "IMMERSION GOLD (ENIG)" at 314.819,82.345 h1.52
  text "ENEPIG" at 348.793,82.162 h1.52
  text "SURFACE FINISH:" at 287.87,82.136 h1.52
  text "X" at 310.298,82.136 h1.52
  text "IMM. TIN/SILVER OR EQUIV" at 296.24,78.649 h1.52
  text "OTHER" at 332.599,78.549 h1.52
  text "ARRAY/PANEL:" at 287.87,74.602 h1.52
  text "CUT AND TRIM PER M1 BOARD OUTLINE" at 314.819,74.393 h1.52
  text "N.C. ROUTE" at 314.819,70.94 h1.52
  text "X" at 332.295,70.94 h1.52
  text "V. SCORE" at 336.816,70.94 h1.52
  text "CERTIFICATION:" at 287.87,67.66 h1.52
  text "MATERIALS AND WORKMANSHIP FOR ALL PCBS" at 306.285,67.66 h1.52
  text "TO MEET OR EXCEED THE REQUIREMENTS OF:" at 306.285,65.271 h1.52
  text "X" at 297.078,62.003 h1.52
  text "ANSI IPC-A-600F CLASS ->" at 300.329,62.003 h1.52
  text "X" at 342.188,62.003 h1.52
  text "2" at 344.982,62.003 h1.52
  text "1" at 336.981,61.965 h1.52
  text "3" at 353.973,61.965 h1.52
  text "X" at 317.702,58.252 h1.52
  text "RoHS" at 320.953,58.252 h1.52
  text "OTHER" at 337.321,58.252 h1.52
  text "PER ORDER" at 347.407,58.252 h1.52
  text "ALL BOARDS MUST MEET OR EXCEED UL94-V0 REQUIREMENTS." at 288.569,54.345 h1.52
  text "PCB MUST BEAR THE UL94V-0 UL REGISTERED MATERIAL ID NUMBER" at 288.569,51.397 h1.52
  text "ADDITIONAL REQUIREMENTS:" at 287.87,47.094 h1.52
  text "MICROSECTION:" at 289.769,44.373 h1.52
  text "YES" at 312.775,44.373 h1.52
  text "REQUIRED" at 334.657,40.707 h1.52
  text "BARE BOARD ELEC. TEST:" at 289.769,40.634 h1.52
  text "NONE" at 322.935,40.634 h1.52
  text "X" at 331.66,40.634 h1.52
  text "PER ORDER" at 349.693,40.634 h1.52
  text "XX MIL VIAS REQUIRE NON-CONDUCTIVE FILL AND PLANARIZE" at 294.04,35.428 h1.5
  text "X" at 291.26,32.934 h1.52
  text "XX MIL VIAS REQUIRE CONDUCTIVE FILL AND PLANARIZE" at 294.243,32.787 h1.52
  text "OUTER XX MIL TRACES REQUIRE 50 OHM SINGLE-ENDED IMPEDANCE" at 294.218,28.637 h1.47
  text "LAYER 2 & 3 (INNER LAYERS) XX MIL WIDE, XX MIL SPACE / TRACES REQUIRE 100 OHM DIFFERENTIAL IMPEDANCE" at 294.015,22.65 h1.52
  text ".Layer_Name" at 14.656,-21.806 h1.52
M11 Gerber Information:
  lines w0.254: -7.417,-23.626 160.223,-23.626 ; -7.417,-18.462 160.274,-18.462 ; -7.417,-13.297 -7.417,-28.791 94.31,-28.791 160.274,-28.791 160.274,-13.297 -7.404,-13.297 -7.404,-28.791 32.614,-28.791 ; 55.194,-28.791 55.194,-13.297 ; 87.376,-18.462 87.376,-13.297 ; 108.712,-18.462 108.712,-13.297 ; 124.511,-28.956 124.511,-23.804
  text "ALL ARTWORK VIEWED FROM TOP SIDE" at -5.804,-16.654 h1.52
  text "BOARD #:" at 57.099,-16.654 h1.52
  text ".PRJ_Number" at 70.955,-16.654 h1.52
  text "REV:" at 92.405,-16.654 h1.52
  text ".PCB_Rev" at 99.809,-16.654 h1.52
  text "SVN REV:" at 113.69,-16.654 h1.52
  text ".VersionControl_RevNumber" at 126.543,-16.654 h1.52
  text "LAYER NAME =" at -5.804,-21.806 h1.52
  text "TID #:" at 57.099,-21.819 h1.52
  text ".TID" at 70.955,-21.819 h1.52
  text "PLOT NAME =" at -5.804,-27.034 h1.52
  text ".plot_File_Name" at 14.656,-27.034 h1.52
  text "GENERATED    :" at 57.15,-27.034 h1.52
  text ".Print_Date" at 79.235,-27.034 h1.52
  text ".Print_Time" at 97.752,-27.034 h1.52
  text "TEXAS INSTRUMENTS" at 129.87,-27.034 h1.52
M12 Stackup:
  text ".Layer_Name" at 14.656,-21.806 h1.52
M13 Component Bodies Top:
  text ".Layer_Name" at 14.656,-21.806 h1.52
M14 Component Bodies Bottom:
  text ".Layer_Name" at 14.656,-21.806 h1.52
M15 Courtyards Top:
  text ".Layer_Name" at 14.656,-21.806 h1.52
M16 Courtyards Bottom:
  text ".Layer_Name" at 14.656,-21.806 h1.52
Drill Drawing:
  text ".Layer_Name" at 14.656,-21.806 h1.52
M17 Embedded Cavity:
  text ".Layer_Name" at 14.656,-21.806 h1.52
M18 Embedded Assembly:
  text ".Layer_Name" at 14.656,-21.806 h1.52
M19 Embedded Keepout:
  text ".Layer_Name" at 14.656,-21.806 h1.52

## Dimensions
0,-10.16 to 25.4,-10.16 on M2 Board Dimensions
0,0 to -0.1,88.9 on M2 Board Dimensions
0,0 to 164.4,88.9 on M2 Board Dimensions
